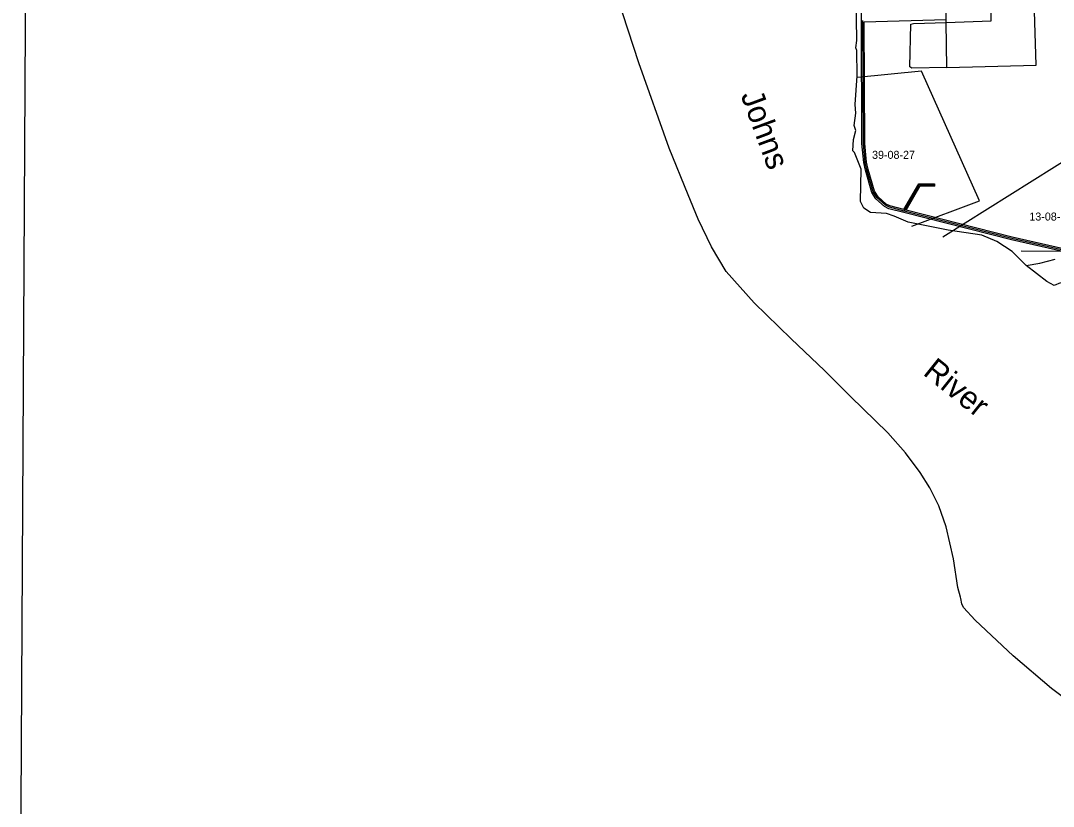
# Model space of a CAD drawing. Extents: x 418523 to 616617, y 1878279 to 2196743.
# Drawn here: x 457897 to 486921, y 1971295 to 1993379 of the extents above; entities that cross this region are included whole.
import ezdxf

# ---------------------------------------------------------------- set-up
doc = ezdxf.new("R2010")
doc.units = 0
for name, color, linetype in [('Level 1', 7, 'Continuous'), ('Level 10', 7, 'Continuous'), ('Level 2', 7, 'Continuous'), ('Level 22', 7, 'Continuous'), ('Level 23', 7, 'Continuous'), ('Level 31', 7, 'Continuous'), ('Level 32', 7, 'Continuous'), ('Level 34', 7, 'Continuous'), ('Level 41', 7, 'Continuous'), ('Level 5', 7, 'Continuous'), ('Level 63', 7, 'Continuous'), ('Level 7', 7, 'Continuous')]:
    doc.layers.add(name, color=color, linetype=linetype)

msp = doc.modelspace()

# ---------------------------------------------------------------- linework, layer by layer
at = {"layer": 'Level 1'}
for p, q in [((495390.078, 1994579.436), (483818.505, 1987290.855)), ((483214.964, 1991956.975), (481418.246, 1991776.936)), ((484842.843, 1988314.105), (483214.964, 1991956.975)), ((482941.318, 1987600.119), (484842.843, 1988314.105)), ((489281.291, 1986873.59), (486013.596, 1986904.071))]:
    msp.add_line(p, q, dxfattribs=at)
at = {"layer": 'Level 10'}
for points in [[(485789.136, 1975525.751), (484722.1, 1976523.764), (484391.087, 1976879.769), (484352.085, 1976987.771), (484322.081, 1977133.774), (484312.08, 1977169.775), (484235.075, 1977441.781), (484114.057, 1978252.799), (483913.037, 1979155.819), (483701.023, 1979745.831), (483451.01, 1980242.84), (483180.996, 1980677.847), (482760.979, 1981231.856), (482270.96, 1981788.864), (481222.922, 1982818.876), (480488.895, 1983546.886), (479547.862, 1984439.896), (478512.824, 1985449.908), (477729.794, 1986323.921), (477311.773, 1987021.932), (476941.751, 1987799.946), (476652.733, 1988486.96), (476123.699, 1989790.985), (475273.638, 1992196.032), (474361.568, 1994982.088)], [(489532.279, 1969485.935), (489504.254, 1972588.722), (489502.25, 1972802.727), (489304.244, 1972927.728), (488749.228, 1973275.731), (488584.223, 1973382.731), (487954.205, 1973794.734), (486865.171, 1974610.741), (485789.136, 1975525.751)]]:
    msp.add_lwpolyline(points, dxfattribs=at)
at = {"layer": 'Level 22'}
for points in [[(482731.175, 1988026.063), (482315.201, 1988132.043), (482198.755, 1988191.146), (481966.295, 1988400.632), (481858.927, 1988567.703), (481678.532, 1989185.707), (481629.41, 1989394.323), (481582.151, 1989928.051), (481565.279, 1993379.351)], [(487606.036, 1986835.578), (485753.941, 1987256.906), (482731.175, 1988026.063)]]:
    msp.add_lwpolyline(points, dxfattribs=at)
at = {"layer": 'Level 23'}
for points in [[(481525.279, 1993379.052), (481520.266, 1994052.129), (481459.755, 1994548.186), (481430.996, 1994555.556), (481186.703, 1995378.896), (481113.763, 1995625.991)], [(482721.299, 1987987.3), (482301.04, 1988094.371), (482175.919, 1988157.878), (481935.54, 1988374.502), (481822.15, 1988550.943), (481639.838, 1989175.512), (481589.817, 1989387.943), (481542.159, 1989926.186), (481525.279, 1993379.155)], [(482721.93, 1988069.696), (482329.361, 1988169.714), (482221.59, 1988224.414), (481997.051, 1988426.763), (481895.705, 1988584.463), (481717.225, 1989195.902), (481669.002, 1989400.704), (481622.144, 1989929.916), (481605.422, 1993350.37)], [(487597.164, 1986796.574), (485744.572, 1987218.015), (482721.31, 1987987.296)], [(487614.91, 1986874.582), (485763.311, 1987295.797), (482782.427, 1988054.296)]]:
    msp.add_lwpolyline(points, dxfattribs=at)
at = {"layer": 'Level 31'}
msp.add_lwpolyline([(482731.175, 1988026.063), (483161.269, 1988761.911), (483582.484, 1988759.926)], dxfattribs=at)
at = {"layer": 'Level 32'}
for p, q in [((481605.422, 1993350.37), (483909.732, 1993409.539)), ((483582.625, 1988789.926), (483582.343, 1988729.925))]:
    msp.add_line(p, q, dxfattribs=at)
for points in [[(482721.929, 1988069.696), (483144.102, 1988791.994), (483582.625, 1988789.926)], [(482782.427, 1988054.296), (483178.435, 1988731.83), (483582.343, 1988729.925)]]:
    msp.add_lwpolyline(points, dxfattribs=at)
at = {"layer": 'Level 5'}
for p, q in [((483910.35, 1993330.496), (483941.222, 1995964.651)), ((483928.523, 1992063.235), (483910.35, 1993330.496))]:
    msp.add_line(p, q, dxfattribs=at)
for points in [[(483928.523, 1992063.235), (486438.119, 1992124.707), (486359.504, 1994551.076), (486366.431, 1995834.847), (486334.924, 1996176.806), (486310.113, 1996210.316), (485834.845, 1996196.19)], [(483910.35, 1993330.496), (485177.733, 1993373.672), (485151.389, 1994674.304)], [(486157.675, 1986499.096), (485759.65, 1986893.071), (485336.008, 1987170.462), (484911.807, 1987347.821), (483962.187, 1987486.313), (482837.992, 1987717.486), (482447.101, 1987886.305), (482230.776, 1987962.514), (481780.747, 1987989.94), (481597.972, 1988107.67), (481498.986, 1988299.934), (481520.5, 1989200.156), (481331.348, 1989676.345), (481289.896, 1989718.256), (481308.3, 1990043.274), (481368.027, 1990293.071), (481327.094, 1990434.983), (481370.609, 1990776.552), (481346.974, 1991026.808), (481409.62, 1991826.768), (481396.836, 1992543.756), (481372.185, 1992610.587), (481398.311, 1992818.862), (481379.969, 1994052.772)], [(483928.523, 1992063.235), (482944.705, 1992043.562), (482886.583, 1992085.543), (482918.032, 1993277.512), (482993.193, 1993302.094), (483910.35, 1993330.496)], [(487122.061, 1986010.356), (486946.61, 1985936.271), (486738.794, 1986045.791), (486157.675, 1986499.096)]]:
    msp.add_lwpolyline(points, dxfattribs=at)
at = {"layer": 'Level 63'}
msp.add_lwpolyline([(457897.306, 1969639.697), (497565.655, 1969446.889), (497762.102, 2014904.337), (458142.925, 2015097.576), (457897.306, 1969639.697)], dxfattribs=at)
at = {"layer": 'Level 7'}
msp.add_lwpolyline([(486157.675, 1986499.096), (486541.501, 1986563.732), (486975.607, 1986678.08)], dxfattribs=at)

# ---------------------------------------------------------------- texts
at = {"layer": 'Level 2'}
for s, p in [('39-08-27', (481825.863, 1989495.163)), ('13-08-27', (486246.715, 1987760.451))]:
    msp.add_text(s, height=225, dxfattribs=at).set_placement(p)
at = {"layer": 'Level 34'}
for s, height, rotation, p in [('COUNTY HWY 13', 25, 270.2790611, (481560.585, 1991783.087)), ('HICKORY LANE', 24.99916, 59.6931527, (482901.227, 1988292.24)), ('COUNTY HWY 13', 25, 345.7231806, (483982.204, 1987695.484))]:
    msp.add_text(s, height=height, rotation=rotation, dxfattribs=at).set_placement(p)
at = {"layer": 'Level 41'}
for s, rotation, p in [('Johns', 290.3113944, (478127.173, 1991284.191)), ('River', 321.2877, (483229.061, 1983444.661))]:
    msp.add_text(s, height=640, rotation=rotation, dxfattribs=at).set_placement(p)

doc.saveas('drawing.dxf')
